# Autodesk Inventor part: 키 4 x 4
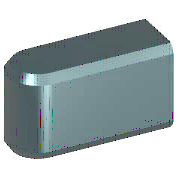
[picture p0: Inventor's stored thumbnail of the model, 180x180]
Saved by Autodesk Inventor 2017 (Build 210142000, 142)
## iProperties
IsCustomPart: 1
Created: 2012-02
Part Number: 키 4 x 4
Material: 강철, 연강
Description: 키 및 해당 키홈
Document SubType Name: Modeling
Standard: KS B 1311
Designer: mduedu
Standards Organization: KS
Language: ko-KR
Size Designation: 4 x 4 x 18
Categories: <MemberInstance><Categories><Category DisplayName="샤프트 부품" InternalName="7f7aeb1f-a693-4053-b835-cee3144e0d98" Mnemonic="SHFT"><Category DisplayName="키" Interna
Density: 1 g/cm^3
Appearance: 주황색
Author: mduedu
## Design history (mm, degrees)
sketch "스케치1"
  geometry: L1 (2, 2)-(18, 2); L2 (18, 2)-(18, -2); L3 (18, -2)-(2, -2); L4 (0, 7)-(0, -7) reference; L5 (-5, 0)-(30, 0) reference; A1 r 2 centre (2, 0) between (2, 2) and (2, -2)
  constraints: 6 end point, 3 tangent, 2 point on circle, 1 centre point, 1 horizontal, 1 parallel, 1 perpendicular, 1 point on line
  dimensions: "d0" = 2 radius of A1 (= 0.5 x PB); "d7" = 18 distance between parallel lines of L2 L4 (= NLG)
workplane "Work Plane1"
workplane "Work Plane2"
extrude "본체1" new body sketch "스케치1" taper "d3" = 0 deg; stored distance "d4" = 10
workaxis "Work Axis1"
workplane "Work Plane4"
body "Solid1"
chamfer "모따기1" distance "d8" = 0.25 (= PHH); stored, may be unused: second distance "d9" = 0.25 (= PHH), angle "d13" = 45 deg
other parameters: "d1" = -2.5 (= -PNT), "d2" = 1.5 (= PH - PNT), "NLG" = 18 [user parameter; used in 2 equation terms], "PB" = 4 [user parameter; used in 1 equation term], "PNT" = 2.5 [user parameter; used in 2 equation terms], "PH" = 4 [user parameter; used in 1 equation term], "PHH" = 0.25 [user parameter; used in 2 equation terms], "d10" = 0, "d16" = 0, "d17" = 0, "d18" = 0, "RR" = 0.08 [user parameter], "WDMAX" = 12 [user parameter], "PLB1" = 18 (= NLG) [user parameter], "PUEB" = 1.8 [user parameter]
